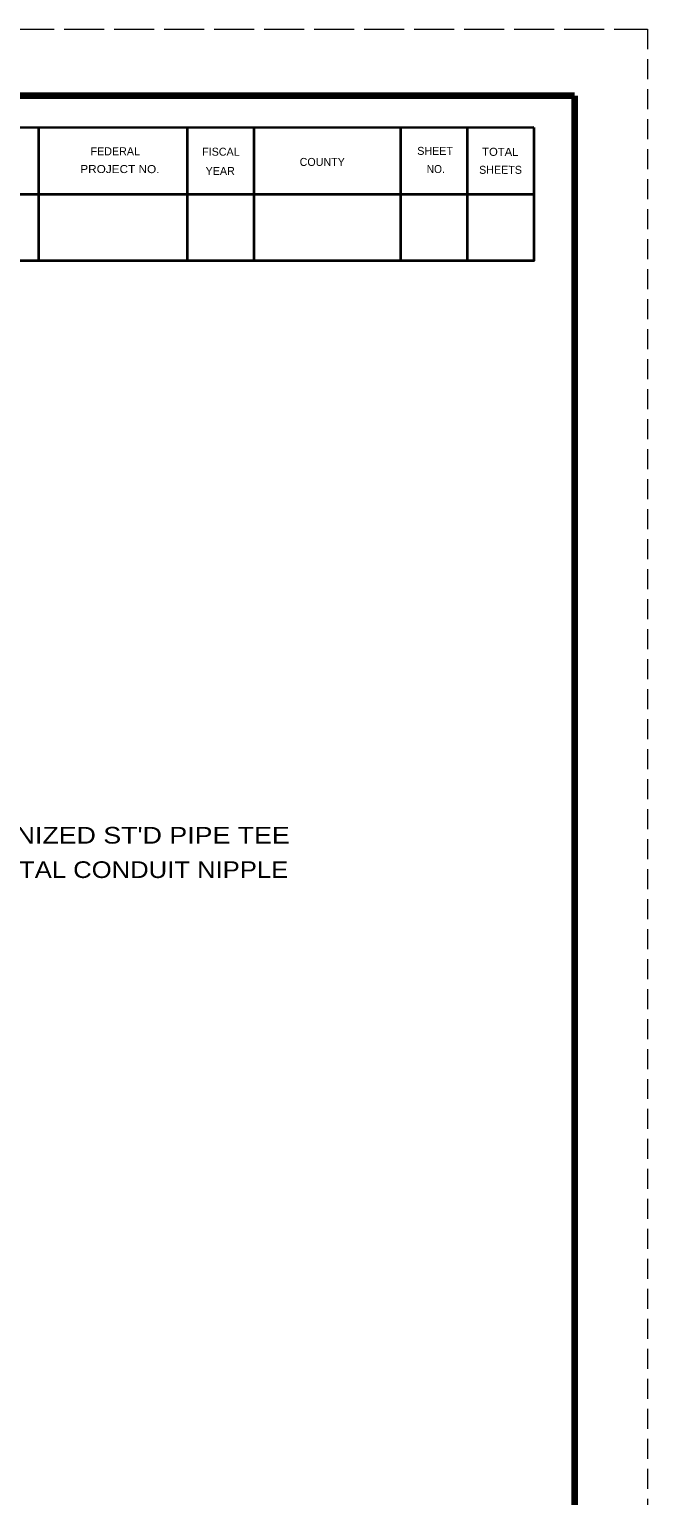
# Model space of a CAD drawing. Extents: x -1 to 679, y 0 to 440.
# Drawn here: x 585.9 to 678.6, y 219.8 to 439.8 of the extents above; entities that cross this region are included whole.
import ezdxf

# ---------------------------------------------------------------- set-up
doc = ezdxf.new("R2010")
doc.units = 0
doc.linetypes.add('LONG_DASHED', pattern=[7.5, 6, -1.5])
doc.linetypes.add('MEDIUM_DASHED', pattern=[4.5, 3, -1.5])
doc.layers.add('1', color=7, linetype='Continuous', lineweight=35)
doc.layers.add('61', color=7, linetype='Continuous', lineweight=35)

msp = doc.modelspace()

# ---------------------------------------------------------------- linework, layer by layer
at = {"layer": '1', "linetype": 'MEDIUM_DASHED', "lineweight": 13}
msp.add_line((678.644, 439.785), (678.624, -0.235), dxfattribs=at)
at = {"layer": '61', "linetype": 'LONG_DASHED', "lineweight": 13}
msp.add_line((-1.376, 439.785), (678.644, 439.785), dxfattribs=at)
at = {"layer": '61', "lineweight": 158}
msp.add_line((667.664, 429.785), (667.684, 9.745), dxfattribs=at)
at = {"layer": '61'}
for p, q in [((587.264, 425.025), (587.264, 405.025)), ((609.584, 425.025), (609.584, 405.025)), ((619.584, 425.025), (619.584, 405.025)), ((641.564, 425.045), (641.564, 405.045)), ((651.564, 425.045), (651.564, 405.045)), ((661.584, 415.005), (553.564, 415.025))]:
    msp.add_line(p, q, dxfattribs=at)
at = {"layer": '61', "lineweight": 158}
msp.add_lwpolyline([(667.664, 429.785), (28.624, 429.785), (28.624, 9.765)], dxfattribs=at)
at = {"layer": '61'}
for points in [[(661.564, 425.045), (553.584, 425.025), (553.584, 405.025)], [(661.564, 425.045), (661.564, 405.045), (553.584, 405.025)]]:
    msp.add_lwpolyline(points, dxfattribs=at)

# ---------------------------------------------------------------- texts
at = {"layer": '1'}
for s, width, p in [("GALVANIZED ST'D PIPE TEE", 1.2, (570.472, 317.605)), ('1/2" METAL CONDUIT NIPPLE', 1.15, (570.816, 312.447))]:
    msp.add_text(s, height=2.5, dxfattribs=dict(at, width=width)).set_placement(p)
at = {"layer": '61'}
for s, rotation, p in [('FEDERAL', 0.007, (595.084, 420.885)), ('FISCAL', 359.942, (611.824, 420.825)), ('COUNTY', 0.069, (626.444, 419.285)), ('SHEET', 0.059, (644.084, 420.945)), ('YEAR', 0.105, (612.344, 417.925)), ('SHEETS', 359.959, (653.364, 418.105))]:
    msp.add_text(s, height=1.201, rotation=rotation, dxfattribs=at).set_placement(p)
for s, rotation, width, p in [('TOTAL', 359.926, 1.05, (653.824, 420.805)), ('PROJECT NO.', 359.922, 1.1, (593.544, 418.225)), ('NO.', 359.852, 0.95, (645.504, 418.225))]:
    msp.add_text(s, height=1.201, rotation=rotation, dxfattribs=dict(at, width=width)).set_placement(p)

doc.saveas('drawing.dxf')
